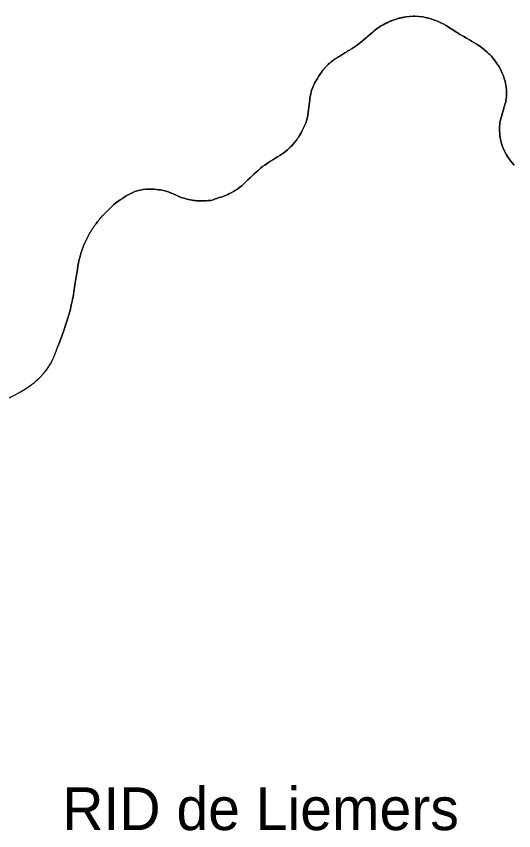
# Model space of a CAD drawing. Extents: x 113371 to 291721, y 393993 to 520143.
# Drawn here: x 196722 to 202548, y 438114 to 447641 of the extents above; entities that cross this region are included whole.
import ezdxf

# ---------------------------------------------------------------- set-up
doc = ezdxf.new("R2010")
doc.units = 0
doc.layers.add('Default', color=7, linetype='Continuous')
doc.layers.add('plaatsnamen', color=7, linetype='Continuous')

msp = doc.modelspace()

# ---------------------------------------------------------------- linework, layer by layer
at = {"layer": 'Default'}
for points in [[(200627.035625, 447246.5725), (200640.015625, 447254.6325), (200655.035625, 447263.9125), (200668.055625, 447271.8725), (200677.065625, 447278.3925), (200702.755625, 447295.6225), (200735.435625, 447319.6025), (200754.805625, 447334.2125), (200777.745625, 447353.4525), (200803.935625, 447375.7125), (200820.385625, 447390.1025), (200829.785625, 447398.7925), (200856.485625, 447421.9725), (200895.555625, 447456.4225), (200903.825625, 447463.5225), (200914.445625, 447472.5425), (200937.895625, 447492.2025), (200985.935625, 447525.9325), (201018.205625, 447541.3525), (201038.435625, 447552.5425), (201043.215625, 447555.2225), (201044.695625, 447556.0525), (201057.715625, 447562.6525), (201063.965625, 447565.9225), (201075.625625, 447571.5325), (201085.445625, 447576.3825), (201091.945625, 447578.3525), (201101.835625, 447582.4425), (201106.505625, 447584.7725), (201109.965625, 447585.9825), (201116.925625, 447588.4025), (201123.105625, 447590.9825), (201194.595625, 447615.4125), (201203.855625, 447617.7325), (201217.875625, 447620.6825), (201225.785625, 447623.4825), (201231.145625, 447624.6125), (201238.625625, 447625.9225)], [(201539.175625, 447622.0925), (201526.885625, 447624.6625), (201482.585625, 447633.9425), (201434.525625, 447639.3925), (201389.625625, 447641.0825), (201369.655625, 447641.0225), (201282.945625, 447635.4625), (201258.945625, 447629.4525), (201252.405625, 447628.6025), (201247.695625, 447627.5025), (201238.625625, 447625.9225), (201231.145625, 447624.6125), (201225.785625, 447623.4825), (201217.875625, 447620.6825), (201203.855625, 447617.7325), (201194.595625, 447615.4125), (201123.105625, 447590.9825), (201116.925625, 447588.4025), (201109.965625, 447585.9825), (201106.505625, 447584.7725), (201101.835625, 447582.4425), (201091.945625, 447578.3525), (201085.445625, 447576.3825), (201075.625625, 447571.5325), (201063.965625, 447565.9225), (201057.715625, 447562.6525), (201044.695625, 447556.0525), (201043.215625, 447555.2225), (201038.435625, 447552.5425), (201018.205625, 447541.3525), (200985.935625, 447525.9325), (200937.895625, 447492.2025), (200914.445625, 447472.5425), (200903.825625, 447463.5225), (200895.555625, 447456.4225), (200856.485625, 447421.9725), (200829.785625, 447398.7925), (200820.385625, 447390.1025)], [(201238.625625, 447625.9225), (201247.695625, 447627.5025), (201252.405625, 447628.6025), (201258.945625, 447629.4525), (201282.945625, 447635.4625), (201369.655625, 447641.0225), (201389.625625, 447641.0825), (201434.525625, 447639.3925), (201482.585625, 447633.9425), (201526.885625, 447624.6625), (201539.175625, 447622.0925), (201587.225625, 447607.5925), (201590.365625, 447606.5325), (201607.235625, 447600.8125), (201642.965625, 447587.7325), (201662.455625, 447578.6825), (201692.315625, 447563.9625), (201729.875625, 447549.1025), (201755.285625, 447531.9125), (201794.645625, 447505.7525), (201833.015625, 447482.3325), (201853.615625, 447469.5725), (201879.735625, 447453.0625), (201896.345625, 447442.7825), (201916.915625, 447429.8525), (201962.065625, 447404.2225), (201994.505625, 447386.0225), (202038.285625, 447361.4925), (202054.905625, 447351.2125), (202082.115625, 447333.7525), (202106.385625, 447318.7225), (202130.385625, 447303.6825), (202149.105625, 447290.2325), (202183.915625, 447265.1825), (202205.335625, 447247.9825), (202237.505625, 447221.0825), (202257.555625, 447202.8925), (202267.575625, 447192.8625)], [(202436.795625, 446911.8625), (202426.915625, 446943.8725), (202413.485625, 446973.8325), (202392.165625, 447021.0725), (202376.055625, 447049.5225), (202349.915625, 447089.9625), (202325.645625, 447125.0325), (202307.185625, 447148.5025), (202296.115625, 447163.0125), (202285.565625, 447174.0925), (202267.575625, 447192.8625), (202257.555625, 447202.8925), (202237.505625, 447221.0825), (202205.335625, 447247.9825), (202183.915625, 447265.1825), (202149.105625, 447290.2325), (202130.385625, 447303.6825), (202106.385625, 447318.7225), (202082.115625, 447333.7525), (202054.905625, 447351.2125), (202038.285625, 447361.4925), (201994.505625, 447386.0225), (201962.065625, 447404.2225), (201916.915625, 447429.8525), (201896.345625, 447442.7825), (201879.735625, 447453.0625), (201853.615625, 447469.5725), (201833.015625, 447482.3325), (201794.645625, 447505.7525), (201755.285625, 447531.9125), (201729.875625, 447549.1025), (201692.315625, 447563.9625), (201662.455625, 447578.6825), (201642.965625, 447587.7325), (201607.235625, 447600.8125), (201590.365625, 447606.5325), (201587.225625, 447607.5925), (201539.175625, 447622.0925)], [(200820.385625, 447390.1025), (200803.935625, 447375.7125), (200777.745625, 447353.4525), (200754.805625, 447334.2125), (200735.435625, 447319.6025), (200702.755625, 447295.6225), (200677.065625, 447278.3925), (200668.055625, 447271.8725), (200655.035625, 447263.9125), (200640.015625, 447254.6325), (200627.035625, 447246.5725), (200614.385625, 447239.2225), (200614.005625, 447238.9825), (200602.225625, 447231.4825), (200591.935625, 447225.3825), (200585.895625, 447222.1625), (200579.785625, 447218.2825), (200574.695625, 447215.4925), (200570.215625, 447212.6425), (200533.595625, 447190.9825), (200522.045625, 447184.0725), (200510.305625, 447176.3325), (200495.075625, 447166.7625), (200483.535625, 447159.7225), (200476.105625, 447154.6725), (200471.985625, 447152.3525), (200465.285625, 447149.0525), (200455.585625, 447142.2125), (200451.335625, 447140.0625), (200441.055625, 447132.4725), (200434.545625, 447127.3525), (200425.075625, 447120.8225), (200409.795625, 447108.2025), (200400.205625, 447098.7525), (200393.885625, 447094.4525), (200383.945625, 447086.8425), (200374.495625, 447077.5225), (200365.455625, 447068.6825)], [(200288.215625, 446976.0525), (200299.135625, 446991.5825), (200301.685625, 446995.2425), (200312.275625, 447009.2425), (200321.115625, 447019.7025), (200330.425625, 447030.6125), (200335.765625, 447037.0725), (200344.295625, 447047.6325), (200350.875625, 447053.1925), (200356.875625, 447060.3725), (200365.455625, 447068.6825), (200374.495625, 447077.5225), (200383.945625, 447086.8425), (200393.885625, 447094.4525), (200400.205625, 447098.7525), (200409.795625, 447108.2025), (200425.075625, 447120.8225), (200434.545625, 447127.3525), (200441.055625, 447132.4725), (200451.335625, 447140.0625), (200455.585625, 447142.2125), (200465.285625, 447149.0525), (200471.985625, 447152.3525), (200476.105625, 447154.6725), (200483.535625, 447159.7225), (200495.075625, 447166.7625), (200510.305625, 447176.3325), (200522.045625, 447184.0725), (200533.595625, 447190.9825), (200570.215625, 447212.6425), (200574.695625, 447215.4925), (200579.785625, 447218.2825), (200585.895625, 447222.1625), (200591.935625, 447225.3825), (200602.225625, 447231.4825), (200614.005625, 447238.9825), (200614.385625, 447239.2225), (200627.035625, 447246.5725)], [(202267.575625, 447192.8625), (202285.565625, 447174.0925), (202296.115625, 447163.0125), (202307.185625, 447148.5025), (202325.645625, 447125.0325), (202349.915625, 447089.9625), (202376.055625, 447049.5225), (202392.165625, 447021.0725), (202413.485625, 446973.8325), (202426.915625, 446943.8725), (202436.795625, 446911.8625), (202443.385625, 446889.2725), (202446.215625, 446876.5625), (202450.915625, 446857.2625), (202458.445625, 446810.6525), (202462.685625, 446773.0025), (202462.215625, 446731.5725), (202461.745625, 446701.9225), (202459.395625, 446680.2625), (202455.535625, 446657.8425), (202453.275625, 446640.2525), (202451.485625, 446630.7425), (202448.655625, 446620.3925), (202439.545625, 446590.7725), (202439.345625, 446590.2625), (202433.375625, 446572.7325), (202430.615625, 446562.9225), (202423.855625, 446536.8025), (202416.195625, 446512.5225), (202402.385625, 446468.3625), (202395.755625, 446443.2025), (202385.045625, 446400.1725), (202384.265625, 446387.2825), (202380.495625, 446341.1525), (202380.965625, 446303.4925), (202383.325625, 446257.8325), (202385.205625, 446237.1225), (202391.885625, 446204.5425)], [(200365.455625, 447068.6825), (200356.875625, 447060.3725), (200350.875625, 447053.1925), (200344.295625, 447047.6325), (200335.765625, 447037.0725), (200330.425625, 447030.6125), (200321.115625, 447019.7025), (200312.275625, 447009.2425), (200301.685625, 446995.2425), (200299.135625, 446991.5825), (200288.215625, 446976.0525), (200262.385625, 446936.8225), (200253.785625, 446921.4425), (200247.685625, 446911.4825), (200214.265625, 446857.0425), (200205.865625, 446837.3025), (200204.105625, 446833.1725), (200198.285625, 446819.4925), (200189.945625, 446799.2125), (200180.705625, 446772.8925), (200176.515625, 446757.5025), (200170.055625, 446733.7925), (200164.145625, 446705.6425), (200162.235625, 446691.6325), (200161.405625, 446685.5325), (200158.005625, 446659.1025), (200154.635625, 446627.0025), (200153.095625, 446613.3925), (200147.915625, 446573.5825), (200145.525625, 446551.1925), (200140.545625, 446514.8825), (200134.485625, 446480.0925), (200126.835625, 446444.0225), (200115.705625, 446401.6325), (200108.995625, 446382.3625), (200089.365625, 446344.1725), (200079.145625, 446321.0025), (200071.125625, 446303.6925)], [(199934.515625, 446112.9625), (199948.545625, 446126.7925), (199960.995625, 446140.7925), (199981.055625, 446163.9125), (200002.225625, 446191.2025), (200012.625625, 446205.6825), (200022.145625, 446219.1025), (200040.445625, 446246.9325), (200050.845625, 446264.5125), (200061.875625, 446285.0125), (200071.125625, 446303.6925), (200079.145625, 446321.0025), (200089.365625, 446344.1725), (200108.995625, 446382.3625), (200115.705625, 446401.6325), (200126.835625, 446444.0225), (200134.485625, 446480.0925), (200140.545625, 446514.8825), (200145.525625, 446551.1925), (200147.915625, 446573.5825), (200153.095625, 446613.3925), (200154.635625, 446627.0025), (200158.005625, 446659.1025), (200161.405625, 446685.5325), (200162.235625, 446691.6325), (200164.145625, 446705.6425), (200170.055625, 446733.7925), (200176.515625, 446757.5025), (200180.705625, 446772.8925), (200189.945625, 446799.2125), (200198.285625, 446819.4925), (200204.105625, 446833.1725), (200205.865625, 446837.3025), (200214.265625, 446857.0425), (200247.685625, 446911.4825), (200253.785625, 446921.4425), (200262.385625, 446936.8225), (200288.215625, 446976.0525)], [(202551.555625, 445899.4225), (202530.375625, 445924.8425), (202501.195625, 445962.5025), (202475.305625, 446000.6325), (202462.125625, 446021.3425), (202434.255625, 446071.3325), (202423.425625, 446097.2225), (202412.595625, 446125.4625), (202406.675625, 446145.7625), (202405.635625, 446147.8425), (202391.885625, 446204.5425), (202385.205625, 446237.1225), (202383.325625, 446257.8325), (202380.965625, 446303.4925), (202380.495625, 446341.1525), (202384.265625, 446387.2825), (202385.045625, 446400.1725), (202395.755625, 446443.2025), (202402.385625, 446468.3625), (202416.195625, 446512.5225), (202423.855625, 446536.8025), (202430.615625, 446562.9225), (202433.375625, 446572.7325), (202439.345625, 446590.2625), (202439.545625, 446590.7725), (202448.655625, 446620.3925), (202451.485625, 446630.7425), (202453.275625, 446640.2525), (202455.535625, 446657.8425), (202459.395625, 446680.2625), (202461.745625, 446701.9225), (202462.215625, 446731.5725), (202462.685625, 446773.0025), (202458.445625, 446810.6525), (202450.915625, 446857.2625), (202446.215625, 446876.5625), (202443.385625, 446889.2725), (202436.795625, 446911.8625)], [(200071.125625, 446303.6925), (200061.875625, 446285.0125), (200050.845625, 446264.5125), (200040.445625, 446246.9325), (200022.145625, 446219.1025), (200012.625625, 446205.6825), (200002.225625, 446191.2025), (199981.055625, 446163.9125), (199960.995625, 446140.7925), (199948.545625, 446126.7925), (199934.515625, 446112.9625), (199910.285625, 446090.3125), (199896.635625, 446077.6525), (199874.195625, 446060.0125), (199859.825625, 446049.4725), (199832.805625, 446029.8825), (199807.405625, 446012.6525), (199779.535625, 445995.6925), (199762.185625, 445984.7525), (199724.745625, 445962.3425), (199698.185625, 445945.4925), (199665.095625, 445922.8625), (199633.775625, 445901.3325), (199607.035625, 445881.9225), (199582.315625, 445862.5225), (199565.555625, 445848.7025), (199549.735625, 445834.9825), (199529.765625, 445817.5325), (199508.545625, 445798.1525), (199484.575625, 445774.9625), (199459.175625, 445749.9525), (199435.245625, 445726.5425), (199398.255625, 445691.0225), (199365.725625, 445660.8825), (199357.075625, 445654.0125), (199339.865625, 445640.5525), (199312.415625, 445620.1525), (199290.845625, 445605.6125)], [(202391.885625, 446204.5425), (202405.635625, 446147.8425), (202406.675625, 446145.7625), (202412.595625, 446125.4625), (202423.425625, 446097.2225), (202434.255625, 446071.3325), (202462.125625, 446021.3425), (202475.305625, 446000.6325), (202501.195625, 445962.5025), (202530.375625, 445924.8425), (202551.555625, 445899.4225)], [(199071.705625, 445510.4725), (199097.825625, 445519.3225), (199121.475625, 445525.9325), (199146.555625, 445534.5325), (199160.975625, 445541.1325), (199182.245625, 445549.9625), (199199.915625, 445557.8125), (199219.545625, 445566.3225), (199238.855625, 445576.4725), (199267.325625, 445592.5025), (199290.845625, 445605.6125), (199312.415625, 445620.1525), (199339.865625, 445640.5525), (199357.075625, 445654.0125), (199365.725625, 445660.8825), (199398.255625, 445691.0225), (199435.245625, 445726.5425), (199459.175625, 445749.9525), (199484.575625, 445774.9625), (199508.545625, 445798.1525), (199529.765625, 445817.5325), (199549.735625, 445834.9825), (199565.555625, 445848.7025), (199582.315625, 445862.5225), (199607.035625, 445881.9225), (199633.775625, 445901.3325), (199665.095625, 445922.8625), (199698.185625, 445945.4925), (199724.745625, 445962.3425), (199762.185625, 445984.7525), (199779.535625, 445995.6925), (199807.405625, 446012.6525), (199832.805625, 446029.8825), (199859.825625, 446049.4725), (199874.195625, 446060.0125), (199896.635625, 446077.6525), (199910.285625, 446090.3125), (199934.515625, 446112.9625)], [(198513.195625, 445583.4225), (198500.505625, 445587.7125), (198475.875625, 445594.9825), (198410.215625, 445609.1825), (198390.215625, 445612.3225), (198337.295625, 445617.4225), (198281.635625, 445618.9825), (198247.915625, 445618.9825), (198202.135625, 445613.4225), (198153.525625, 445603.2225), (198111.935625, 445591.6125), (198071.385625, 445572.9825), (198010.025625, 445539.0125), (197964.245625, 445509.0325), (197939.065625, 445493.1625), (197884.065625, 445453.7225), (197862.125625, 445435.2525), (197837.685625, 445412.0325), (197793.895625, 445369.3025), (197734.305625, 445311.0925), (197728.835625, 445305.0625), (197723.415625, 445298.9925), (197718.035625, 445292.8725), (197712.715625, 445286.7025), (197707.445625, 445280.4925), (197702.235625, 445274.2425), (197697.065625, 445267.9525), (197691.955625, 445261.6125), (197686.895625, 445255.2325), (197681.885625, 445248.8125), (197676.935625, 445242.3425), (197672.035625, 445235.8425), (197657.535625, 445216.6525), (197652.225625, 445209.6125), (197646.965625, 445202.5425), (197641.775625, 445195.4225), (197636.635625, 445188.2525), (197631.565625, 445181.0525)], [(198111.935625, 445591.6125), (198153.525625, 445603.2225), (198202.135625, 445613.4225), (198247.915625, 445618.9825), (198281.635625, 445618.9825), (198337.295625, 445617.4225), (198390.215625, 445612.3225), (198410.215625, 445609.1825), (198475.875625, 445594.9825), (198500.505625, 445587.7125), (198513.195625, 445583.4225), (198538.195625, 445573.7125), (198558.905625, 445563.8225), (198576.445625, 445555.2425), (198585.585625, 445551.3225), (198603.755625, 445543.9725), (198632.485625, 445530.5425), (198664.205625, 445518.6025), (198688.835625, 445511.5125), (198706.745625, 445505.9125), (198723.165625, 445501.4325), (198738.465625, 445497.3325), (198757.575625, 445493.1525), (198782.195625, 445489.4225), (198800.485625, 445486.8125), (198819.145625, 445484.2025), (198829.965625, 445483.8225), (198843.765625, 445482.7025), (198855.635625, 445482.5025), (198876.335625, 445482.2525), (198903.085625, 445482.5025), (198925.805625, 445483.5225), (198943.725625, 445484.0225), (198968.465625, 445484.7825), (198999.005625, 445487.3025), (199027.015625, 445495.1325), (199050.485625, 445503.7125), (199071.705625, 445510.4725)], [(199290.845625, 445605.6125), (199267.325625, 445592.5025), (199238.855625, 445576.4725), (199219.545625, 445566.3225), (199199.915625, 445557.8125), (199182.245625, 445549.9625), (199160.975625, 445541.1325), (199146.555625, 445534.5325), (199121.475625, 445525.9325), (199097.825625, 445519.3225), (199071.705625, 445510.4725), (199050.485625, 445503.7125), (199027.015625, 445495.1325), (198999.005625, 445487.3025), (198968.465625, 445484.7825), (198943.725625, 445484.0225), (198925.805625, 445483.5225), (198903.085625, 445482.5025), (198876.335625, 445482.2525), (198855.635625, 445482.5025), (198843.765625, 445482.7025), (198829.965625, 445483.8225), (198819.145625, 445484.2025), (198800.485625, 445486.8125), (198782.195625, 445489.4225), (198757.575625, 445493.1525), (198738.465625, 445497.3325), (198723.165625, 445501.4325), (198706.745625, 445505.9125), (198688.835625, 445511.5125), (198664.205625, 445518.6025), (198632.485625, 445530.5425), (198603.755625, 445543.9725), (198585.585625, 445551.3225), (198576.445625, 445555.2425), (198558.905625, 445563.8225), (198538.195625, 445573.7125), (198513.195625, 445583.4225)], [(197584.705625, 445107.7425), (197589.055625, 445115.1525), (197593.475625, 445122.5225), (197597.955625, 445129.8525), (197602.495625, 445137.1525), (197607.095625, 445144.4125), (197611.865625, 445151.8225), (197616.695625, 445159.1825), (197621.595625, 445166.5125), (197626.545625, 445173.8025), (197631.565625, 445181.0525), (197636.635625, 445188.2525), (197641.775625, 445195.4225), (197646.965625, 445202.5425), (197652.225625, 445209.6125), (197657.535625, 445216.6525), (197672.035625, 445235.8425), (197676.935625, 445242.3425), (197681.885625, 445248.8125), (197686.895625, 445255.2325), (197691.955625, 445261.6125), (197697.065625, 445267.9525), (197702.235625, 445274.2425), (197707.445625, 445280.4925), (197712.715625, 445286.7025), (197718.035625, 445292.8725), (197723.415625, 445298.9925), (197728.835625, 445305.0625), (197734.305625, 445311.0925), (197793.895625, 445369.3025), (197837.685625, 445412.0325), (197862.125625, 445435.2525), (197884.065625, 445453.7225), (197939.065625, 445493.1625), (197964.245625, 445509.0325), (198010.025625, 445539.0125), (198071.385625, 445572.9825), (198111.935625, 445591.6125)], [(197631.565625, 445181.0525), (197626.545625, 445173.8025), (197621.595625, 445166.5125), (197616.695625, 445159.1825), (197611.865625, 445151.8225), (197607.095625, 445144.4125), (197602.495625, 445137.1525), (197597.955625, 445129.8525), (197593.475625, 445122.5225), (197589.055625, 445115.1525), (197584.705625, 445107.7425), (197580.415625, 445100.2925), (197576.185625, 445092.8225), (197572.015625, 445085.3025), (197567.915625, 445077.7525), (197563.875625, 445070.1725), (197559.895625, 445062.5525), (197555.985625, 445054.9025), (197552.135625, 445047.2225), (197547.985625, 445039.1725), (197543.915625, 445031.0925), (197539.905625, 445022.9825), (197535.965625, 445014.8325), (197532.095625, 445006.6525), (197528.305625, 444998.4425), (197524.575625, 444990.1925), (197520.925625, 444981.9125), (197517.345625, 444973.6025), (197513.835625, 444965.2625), (197510.395625, 444956.8925), (197507.025625, 444948.4925), (197503.735625, 444940.0625), (197500.515625, 444931.6025), (197497.365625, 444923.1225), (197494.295625, 444914.6125), (197491.295625, 444906.0725), (197488.365625, 444897.5125), (197485.515625, 444888.9225)], [(197458.595625, 444791.8825), (197460.975625, 444801.6725), (197463.415625, 444811.4425), (197465.935625, 444821.1925), (197468.525625, 444830.9325), (197471.175625, 444840.6425), (197473.905625, 444850.3425), (197476.705625, 444860.0225), (197479.565625, 444869.6725), (197482.505625, 444879.3125), (197485.515625, 444888.9225), (197488.365625, 444897.5125), (197491.295625, 444906.0725), (197494.295625, 444914.6125), (197497.365625, 444923.1225), (197500.515625, 444931.6025), (197503.735625, 444940.0625), (197507.025625, 444948.4925), (197510.395625, 444956.8925), (197513.835625, 444965.2625), (197517.345625, 444973.6025), (197520.925625, 444981.9125), (197524.575625, 444990.1925), (197528.305625, 444998.4425), (197532.095625, 445006.6525), (197535.965625, 445014.8325), (197539.905625, 445022.9825), (197543.915625, 445031.0925), (197547.985625, 445039.1725), (197552.135625, 445047.2225), (197555.985625, 445054.9025), (197559.895625, 445062.5525), (197563.875625, 445070.1725), (197567.915625, 445077.7525), (197572.015625, 445085.3025), (197576.185625, 445092.8225), (197580.415625, 445100.2925), (197584.705625, 445107.7425)], [(197485.515625, 444888.9225), (197482.505625, 444879.3125), (197479.565625, 444869.6725), (197476.705625, 444860.0225), (197473.905625, 444850.3425), (197471.175625, 444840.6425), (197468.525625, 444830.9325), (197465.935625, 444821.1925), (197463.415625, 444811.4425), (197460.975625, 444801.6725), (197458.595625, 444791.8825), (197456.295625, 444782.0725), (197454.055625, 444772.2525), (197451.895625, 444762.4125), (197449.805625, 444752.5625), (197447.785625, 444742.6925), (197445.835625, 444732.8125), (197443.965625, 444722.9125), (197442.155625, 444713.0025), (197433.005625, 444654.0025), (197423.275625, 444591.8625), (197412.385625, 444523.4425), (197403.315625, 444468.0425), (197399.665625, 444445.7825), (197386.255625, 444358.9825), (197381.035625, 444329.9225), (197379.545625, 444322.4725), (197365.885625, 444261.3125), (197351.125625, 444197.9925), (197334.235625, 444138.3925), (197310.225625, 444062.0625), (197277.755625, 443963.9225), (197254.035625, 443898.4925), (197222.885625, 443816.4725), (197209.195712, 443779.621165)], [(197009.105625, 443425.3225), (197040.045625, 443460.5525), (197060.985625, 443484.2525), (197082.825625, 443513.4425), (197096.825625, 443534.2725), (197114.595625, 443563.5425), (197128.765625, 443588.3325), (197151.955625, 443635.7825), (197156.825625, 443646.1125), (197160.675625, 443654.2925), (197173.375625, 443683.3325), (197189.115625, 443724.5525), (197201.735625, 443758.6825), (197209.125625, 443779.4325), (197222.885625, 443816.4725), (197254.035625, 443898.4925), (197277.755625, 443963.9225), (197310.225625, 444062.0625), (197334.235625, 444138.3925), (197351.125625, 444197.9925), (197365.885625, 444261.3125), (197379.545625, 444322.4725), (197381.035625, 444329.9225), (197386.255625, 444358.9825), (197399.665625, 444445.7825), (197403.315625, 444468.0425), (197412.385625, 444523.4425), (197423.275625, 444591.8625), (197433.005625, 444654.0025), (197442.155625, 444713.0025), (197443.965625, 444722.9125), (197445.835625, 444732.8125), (197447.785625, 444742.6925), (197449.805625, 444752.5625), (197451.895625, 444762.4125), (197454.055625, 444772.2525), (197456.295625, 444782.0725), (197458.595625, 444791.8825)], [(196416.245625, 443078.0725), (196456.915625, 443092.1525), (196476.335625, 443100.2125), (196677.465625, 443195.8225), (196710.575625, 443213.3225), (196737.385625, 443227.7325), (196771.785625, 443247.0125), (196811.665625, 443271.3725), (196841.815625, 443289.5525), (196893.005625, 443325.0525), (196913.205625, 443340.2125), (196936.025625, 443358.2525), (196959.555625, 443378.4325), (196986.775625, 443403.4325), (197009.105625, 443425.3225)]]:
    msp.add_lwpolyline(points, dxfattribs=at)

# ---------------------------------------------------------------- texts
at = {"layer": 'plaatsnamen'}
msp.add_text('RID de Liemers', height=500, dxfattribs=at).set_placement((197260.341619, 438120.629935))

doc.saveas('drawing.dxf')
